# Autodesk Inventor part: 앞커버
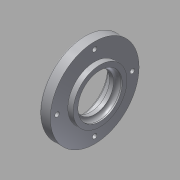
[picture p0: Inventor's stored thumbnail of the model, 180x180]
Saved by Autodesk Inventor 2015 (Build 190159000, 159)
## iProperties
Created: 2015-09
Part Number: 앞커버
Material: 알루미늄 6061
Document SubType Name: Modeling
Designer: mduedu
Density: 2.71 g/cm^3
Mass: 58.9874 g
Surface Area: 98.7754 cm^2
Volume: 21.7666 cm^3
Appearance: 알루미늄 - 평지
Author: mduedu
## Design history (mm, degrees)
sketch "스케치1"
  geometry: L1 (-8, 67)-(-12, 67); L2 (-12, 67)-(-12, 80); L3 (-12, 80)-(-20, 80); L4 (-20, 80)-(-20, 70.5); L5 (-23, 70.5)-(-23, 61); L6 (-23, 61)-(-8, 61); L7 (-8, 61)-(-8, 67); L8 (-79.5, 39.5)-(-79.5, 54.5) reference; L9 (48.5, 54.5)-(48.5, 39.5) reference; L10 (-79.5, 47)-(48.5, 47); L11 (-20, 70.5)-(-23, 70.5); 3 further points
  constraints: 18 end point, 6 parallel, 4 midpoint, 1 horizontal, 1 perpendicular, 1 vertical alignment
  dimensions: "d0" = 15 distance between parallel lines of L7 L5; "d2" = 28 diameter of L6 L10; "d3" = 40 diameter of L1 L10; "d5" = 4 distance of L1.start L1.end; "d6" = 66 diameter of L3 L10; "d7" = 8 distance of L2.end L3.end; "d8" = 47 diameter of L4.end L10
revolve "회전1" sketch "스케치1" stored, may be unused: angle "d4" = 90 deg
sketch "스케치2"
  geometry: C1 r 33 at (0, 0) reference; 2 further points
  constraints: 1 coincident
hole "구멍1" sketch "스케치2" at (0, 0) diameter "d11" = 33; stored, may be unused: countersink angle "d15" = 90 deg, drill point angle "d17" = 0 deg; dims "d12" = 6, "d13" = 4, "d14" = 2, "d16" = 4
fillet "모깎기1" dims "d18" = 3
fillet "모깎기2" dims "d19" = 1
sketch "스케치3"
  geometry: C1 r 33 at (0, 0) reference; 2 further points
  constraints: 1 coincident
hole "구멍2" sketch "스케치3" at (0, 0) diameter "d20" = 40; stored, may be unused: countersink angle "d24" = 90 deg, drill point angle "d26" = 0 deg; dims "d21" = 6, "d22" = 4, "d23" = 2, "d25" = 8
fillet "모깎기3" dims "d27" = 0.4
chamfer "모따기1" distance "d28" = 1; stored, may be unused: second distance "d29" = 2, angle "d30" = 30 deg
sketch "스케치4" dims "d31" = 56
  geometry: C1 r 33 at (0, 0) reference; 6 further points
  constraints: 2 vertical alignment, 1 coincident, 7 other
  dimensions: "d36" = 360 deg dimension on C1.centre point (0, 28) (derived)
sketch "스케치7"
  geometry: 4 further points
hole "구멍4" sketch "스케치7" at (0, 28), (-28, 0), (28, 0), (0, -28) diameter "d48" = 3.4; stored, may be unused: countersink angle "d52" = 90 deg, drill point angle "d54" = 0 deg; dims "d49" = 6, "d50" = 6.5, "d51" = 3.4, "d53" = 8
node "솔리드1"
node "참조1"
node "참조2"
